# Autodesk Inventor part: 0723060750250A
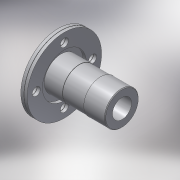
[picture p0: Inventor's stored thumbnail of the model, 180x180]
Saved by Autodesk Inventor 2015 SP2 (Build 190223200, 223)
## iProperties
Created: 2017-02
Part Number: 0723060750250A
Material: PVC-Piping
Description: PLASSON FLANGE ADAPTOR WITH METAL FLANGE 75-2.1/2"
Document SubType Name: Modeling
Designer: KIM
Mass: 92.6774 g
Surface Area: 199.44 cm^2
Volume: 66.1981 cm^3
Density: 1.4 g/cm^3
Appearance: Smooth - White
Author: Кирилл
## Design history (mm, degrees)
derived "872306.ipt"
feature "Solid1::872306.ipt"
tag "TaggingFeature1"
body "Solid1"
other parameters: "d73" = 14.2, "d74" = 90 deg, "d75" = 0.3, "d76" = 185, "d77" = 18, "d78" = 72.5, "d80" = 0, "d82" = 360 deg, "d94" = 65, "d96" = 0.3, "d99" = 360 deg, "d101" = 75, "d103" = 142, "d104" = 1.5, "d107" = 97.5, "d108" = 3.55, "d116" = 73.5, "d117" = 47.33333, "d118" = 47.33333, "d119" = 75, "d120" = 3.75, "d_" = 75, "H_" = 142, "D_" = 185, "Dp_" = 145, "S_" = 18, "DN_" = 65
